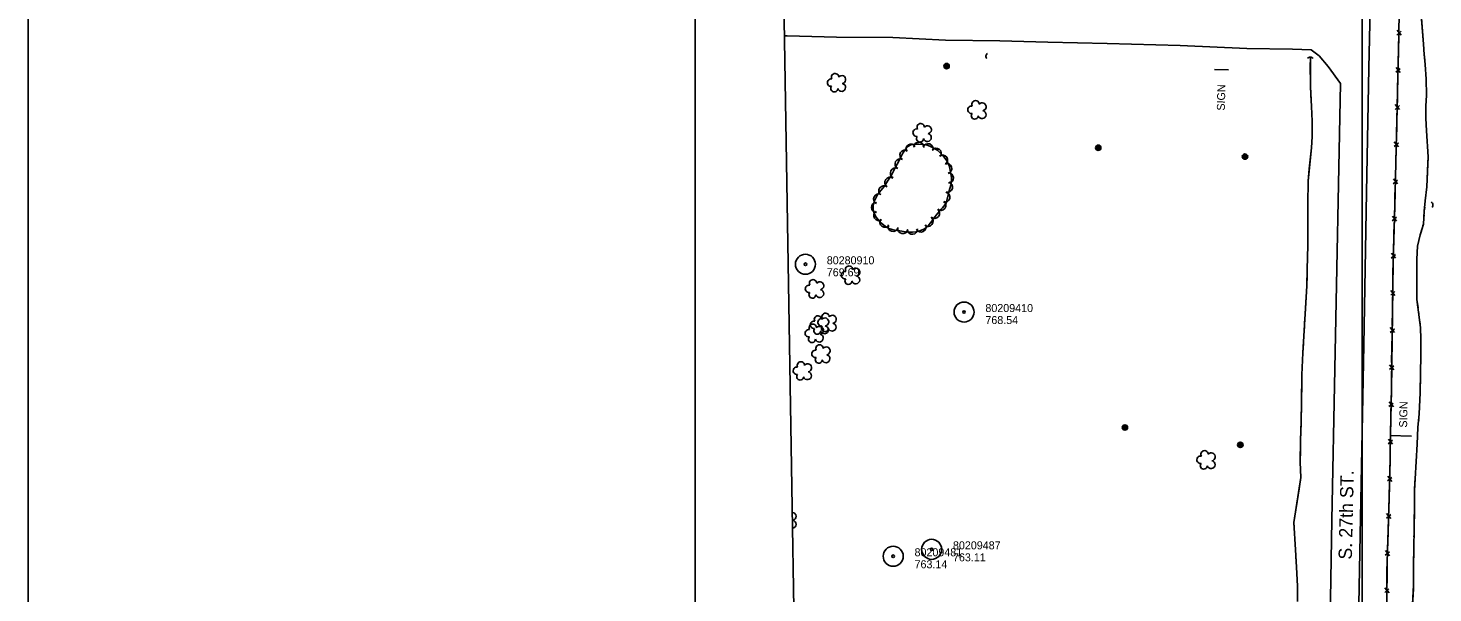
# Model space of a CAD drawing. Extents: x 591954 to 597000, y 198576 to 213500.
# Drawn here: x 593000 to 594053, y 208052 to 208476 of the extents above; entities that cross this region are included whole.
import ezdxf

# ---------------------------------------------------------------- set-up
doc = ezdxf.new("R2010")
doc.units = 0
for name, color, linetype in [('1', 7, 'Continuous'), ('Level 10', 7, 'Continuous'), ('Level 11', 7, 'Continuous'), ('Level 14', 7, 'Continuous'), ('Level 15', 7, 'Continuous'), ('Level 18', 7, 'Continuous'), ('Level 19', 7, 'Continuous'), ('Level 4', 7, 'Continuous'), ('Level 6', 7, 'Continuous')]:
    doc.layers.add(name, color=color, linetype=linetype)

msp = doc.modelspace()

# ---------------------------------------------------------------- linework, layer by layer
at = {"layer": 'Level 10'}
for p, q in [((593000, 207500), (593000, 209000)), ((593500, 207500), (593500, 209000)), ((594000, 207500), (594000, 209000))]:
    msp.add_line(p, q, dxfattribs=at)
at = {"layer": 'Level 11'}
for points in [[(593991.5, 207734.1), (593993.2, 207838.1), (593996.5, 207991.7), (593997.8, 208056.9), (593999.8, 208160.4), (594001.4, 208238.2), (594003.2, 208352.6), (594005, 208445.7), (594007.6, 208557.1), (594009, 208631.5)], [(593567, 208469.8), (593569, 208469.8), (593605.9, 208469), (593648.1, 208468.6), (593687.8, 208466.6), (593728.3, 208466.2), (593764.3, 208465.2), (593808.8, 208464.2), (593863.7, 208462.6), (593913.7, 208460.5), (593947.9, 208460), (593961.7, 208459.4), (593967.7, 208454.9), (593974.6, 208447), (593983.9, 208434.1)], [(593983.9, 208434.1), (593979.6, 208220.4), (593977.3, 208107), (593975.7, 208018.6)]]:
    msp.add_lwpolyline(points, dxfattribs=at)
at = {"layer": 'Level 14'}
for points in [[(593899.8, 208444.3), (593889.4, 208444.6)], [(594036.9, 208169.9), (594020.8, 208170.4)]]:
    msp.add_lwpolyline(points, dxfattribs=at)
for centre, radius in [((593688.5, 208447.2), 2.02), ((593688.4, 208447.2), 1.52), ((593688.5, 208447.2), 1.01), ((593688.5, 208447.2), 0.502), ((593802.2, 208386), 2.02), ((593802.2, 208386), 1.52), ((593802.3, 208386), 1.01), ((593802.3, 208386), 0.502), ((593912.2, 208379.4), 2.02), ((593912.2, 208379.5), 1.52), ((593912.2, 208379.4), 1.01), ((593912.2, 208379.4), 0.502), ((593822.2, 208176.4), 2.02), ((593822.2, 208176.4), 1.52), ((593822.2, 208176.3), 1.01), ((593822.3, 208176.3), 0.502), ((593908.7, 208163.4), 2.02), ((593908.7, 208163.4), 1.52), ((593908.8, 208163.4), 1.01), ((593908.8, 208163.4), 0.502)]:
    msp.add_circle(centre, radius, dxfattribs=at)
at = {"layer": 'Level 15'}
for p, q in [((594029.3, 208470.3), (594026.2, 208474.1)), ((594026.1, 208470.5), (594029.3, 208473.3)), ((594025.3, 208442.7), (594028.6, 208445.4)), ((594028.5, 208442.4), (594025.4, 208446.2)), ((594028, 208414.6), (594024.8, 208418.4)), ((594024.8, 208414.8), (594028, 208417.6)), ((594024, 208387), (594027.3, 208389.7)), ((594027.3, 208386.7), (594024.1, 208390.5)), ((594023.3, 208359.1), (594026.5, 208361.8)), ((594026.5, 208358.9), (594023.4, 208362.7)), ((594022.6, 208331.3), (594025.8, 208334)), ((594025.8, 208331), (594022.7, 208334.8)), ((594021.8, 208303.4), (594025, 208306.1)), ((594025, 208303.2), (594021.9, 208307)), ((594024.6, 208275.3), (594021.4, 208279.1)), ((594021.4, 208275.5), (594024.6, 208278.3)), ((594024.2, 208247.5), (594021, 208251.2)), ((594021, 208247.7), (594024.2, 208250.4)), ((594023.8, 208219.6), (594020.6, 208223.4)), ((594020.6, 208219.8), (594023.8, 208222.6)), ((594020.1, 208192), (594023.3, 208194.7)), ((594023.4, 208191.8), (594020.2, 208195.5)), ((594019.6, 208164.1), (594022.8, 208166.9)), ((594022.8, 208163.9), (594019.7, 208167.7)), ((594019.1, 208136.3), (594022.3, 208139)), ((594022.3, 208136), (594019.2, 208139.8)), ((594018.2, 208108.4), (594021.5, 208111.1)), ((594021.5, 208108.2), (594018.3, 208112)), ((594020.6, 208080.3), (594017.4, 208084.1)), ((594017.3, 208080.6), (594020.6, 208083.3)), ((594016.9, 208052.7), (594020.1, 208055.5)), ((594020.2, 208052.5), (594017, 208056.3))]:
    msp.add_line(p, q, dxfattribs=at)
for points in [[(594011.5, 207735), (594011.8, 207756), (594013.4, 207819.8), (594013.9, 207853.2), (594015.3, 207915.5), (594016.1, 207947.6), (594016.7, 207978.8), (594018.4, 208043.4), (594018.7, 208075.6), (594019.7, 208108), (594020.7, 208140.2), (594021.3, 208172.7), (594021.9, 208204.2), (594023.2, 208300.2), (594024.4, 208341.9), (594025.2, 208374.6), (594026.1, 208406.9), (594026.7, 208438.1), (594027.6, 208471.4), (594027.9, 208504), (594028.7, 208536.2), (594029.2, 208568.7), (594029.8, 208600.4), (594030.8, 208634)], [(594027.3, 208459.2), (594027.6, 208469.2)], [(594027, 208447.9), (594027.3, 208459.2)], [(594026.6, 208431.4), (594026.7, 208438.1), (594026.8, 208441.3)], [(594026.4, 208420), (594026.6, 208431.4)], [(594026, 208403.5), (594026.1, 208406.9), (594026.2, 208413.5)], [(594025.7, 208392.2), (594026, 208403.5)], [(594025.2, 208375.7), (594025.5, 208385.6)], [(594024.9, 208364.3), (594025.2, 208374.6), (594025.2, 208375.7)], [(594024.2, 208336.5), (594024.4, 208341.9), (594024.5, 208347.8)], [(594024.5, 208347.8), (594024.8, 208357.8)], [(594023.8, 208320), (594024.1, 208329.9)], [(594023.4, 208308.6), (594023.8, 208320)], [(594023.1, 208292.1), (594023.2, 208300.2), (594023.3, 208302.1)], [(594022.9, 208280.8), (594023.1, 208292.1)], [(594022.7, 208264.2), (594022.8, 208274.2)], [(594022.5, 208252.9), (594022.7, 208264.2)], [(594022.3, 208236.4), (594022.4, 208246.3)], [(594022.1, 208225.1), (594022.3, 208236.4)], [(594021.9, 208208.5), (594022.1, 208218.5)], [(594021.7, 208197.2), (594021.9, 208204.2), (594021.9, 208208.5)], [(594021.4, 208180.7), (594021.6, 208190.6)], [(594021.2, 208169.4), (594021.3, 208172.7), (594021.4, 208180.7)], [(594020.9, 208152.8), (594021.1, 208162.8)], [(594020.7, 208141.5), (594020.9, 208152.8)], [(594020.2, 208125), (594020.5, 208134.9)], [(594019.9, 208113.6), (594020.2, 208125)], [(594019.4, 208097.1), (594019.7, 208107.1)], [(594019, 208085.8), (594019.4, 208097.1)], [(594018.6, 208069.3), (594018.7, 208075.6), (594018.8, 208079.2)], [(594018.5, 208058), (594018.6, 208069.3)]]:
    msp.add_lwpolyline(points, dxfattribs=at)
for centre, start, end in [((593720.5, 208454.6), 120.5794, 226.819), ((593961.1, 208451.5), 35.2794, 141.519), ((594050.6, 208343.2), 312.9794, 59.219)]:
    msp.add_arc(centre, 2.5, start, end, dxfattribs=at)
at = {"layer": 'Level 18'}
msp.add_lwpolyline([(593688.1, 208344.6), (593689.9, 208351.7), (593690.9, 208355.4), (593692, 208358.8), (593692.1, 208363.7), (593691.3, 208369.3), (593690.4, 208372.8), (593688.2, 208376.9), (593685.8, 208380.1), (593684.3, 208381.8), (593682, 208383.9), (593679, 208385.8), (593675.9, 208387.2), (593673.3, 208388.1), (593671.2, 208388.4), (593667.7, 208388.8), (593665.1, 208388.7), (593662.2, 208388.4), (593659, 208386.7), (593655.6, 208382), (593654.9, 208380.4), (593653.8, 208378.2), (593652.8, 208376), (593651.4, 208373.6), (593649.9, 208370.9), (593648.5, 208367.9), (593646.9, 208365), (593644.8, 208361.7), (593641.6, 208357), (593639.5, 208354.2), (593637, 208351.3), (593634.2, 208345.7), (593633.5, 208342.4), (593633.4, 208339.4), (593634.4, 208336.3), (593635.7, 208334), (593636.9, 208332.4), (593638.6, 208330.3), (593639.9, 208329.2), (593641.5, 208328.1), (593643.5, 208326.6), (593645.2, 208325.6), (593647.7, 208324.7), (593650, 208324.3), (593652.3, 208324), (593657.7, 208322.9), (593660.8, 208322.7), (593663, 208322.8), (593665.5, 208322.9), (593668.4, 208323.7), (593671.4, 208325), (593673, 208326), (593674.6, 208327.4), (593675.5, 208328.5), (593677.4, 208331.1), (593678.2, 208332.3), (593680, 208334.4), (593680.8, 208335.4), (593682, 208336.9), (593683.6, 208338.9), (593684.5, 208339.9), (593685.4, 208341.1), (593688.1, 208344.6)], dxfattribs=at)
for centre, radius, start, end in [((593601.9, 208434.8), 2.78, 78.0716, 279.0826), ((593604.3, 208430.4), 2.61, 140.7797, 358.7123), ((593604.9, 208438.9), 2.78, 1.3946, 209.1675), ((593609.8, 208431.2), 2.97, 196.0745, 79.0477), ((593609.9, 208437.1), 2.97, 278.4237, 139.6575), ((593710.2, 208418.6), 2.78, 1.3946, 209.1675), ((593707.2, 208414.5), 2.78, 78.0716, 279.0826), ((593709.6, 208410.1), 2.61, 140.7797, 358.7123), ((593715.1, 208410.8), 2.97, 196.0745, 79.0477), ((593715.2, 208416.7), 2.97, 278.4237, 139.6575), ((593666.1, 208397.3), 2.78, 78.0716, 279.0826), ((593669.1, 208401.4), 2.78, 1.3946, 209.1675), ((593674.2, 208399.5), 2.97, 278.4237, 139.6575), ((593667.7, 208386.4), 3.85, 358.0589, 178.0435), ((593668.6, 208392.9), 2.61, 140.7797, 358.7123), ((593674.1, 208393.7), 2.97, 196.0745, 79.0477), ((593657.4, 208380.5), 3.85, 59.8995, 239.8841), ((593661.8, 208385), 3.69, 30.7624, 210.7471), ((593674.6, 208385.2), 3.85, 340.9483, 160.933), ((593680.7, 208381.8), 3.84, 321.3979, 141.3826), ((593685.5, 208376.7), 3.85, 305.1599, 125.1445), ((593650.2, 208367), 3.86, 62.5937, 242.5784), ((593653.7, 208373.8), 3.87, 62.1663, 242.1509), ((593688.6, 208370.5), 3.83, 286.6933, 106.678), ((593646.1, 208360.1), 3.87, 56.256, 236.2406), ((593689.1, 208356.5), 3.86, 255.1567, 75.1413), ((593689.8, 208363.4), 3.85, 273.1607, 93.1454), ((593637.6, 208347.6), 3.85, 63.2595, 243.2441), ((593641.5, 208353.7), 3.87, 51.9266, 231.9113), ((593687.1, 208349), 3.87, 256.0559, 76.0405), ((593636, 208341.3), 3.79, 89.9396, 269.9243), ((593637.8, 208335.3), 3.83, 121.6622, 301.6468), ((593679.4, 208336.9), 3.87, 231.1628, 51.1475), ((593684.2, 208342.9), 3.82, 231.5491, 51.5338), ((593642.4, 208330.2), 3.85, 142.299, 322.2837), ((593648.4, 208327.1), 3.83, 163.837, 343.8217), ((593669.4, 208326.7), 3.83, 205.8734, 25.8581), ((593674.5, 208330.9), 3.86, 231.2992, 51.2838), ((593655.7, 208325.5), 3.86, 170.2855, 350.2702), ((593662.9, 208325), 3.85, 183.3457, 3.3304), ((593615.4, 208294.7), 2.78, 1.3946, 209.1675), ((593620.5, 208292.8), 2.97, 278.4237, 139.6575), ((593588.4, 208284.4), 2.78, 1.3946, 209.1675), ((593593.5, 208282.6), 2.97, 278.4237, 139.6575), ((593612.4, 208290.6), 2.78, 78.0716, 279.0826), ((593614.9, 208286.2), 2.61, 140.7797, 358.7123), ((593620.4, 208287), 2.97, 196.0745, 79.0477), ((593585.4, 208280.3), 2.78, 78.0716, 279.0826), ((593587.9, 208275.9), 2.61, 140.7797, 358.7123), ((593593.4, 208276.7), 2.97, 196.0745, 79.0477), ((593588.2, 208251.1), 2.78, 1.3946, 209.1675), ((593589.1, 208253.3), 2.78, 78.0716, 279.0826), ((593592.1, 208257.3), 2.78, 1.3946, 209.1675), ((593594.8, 208255.2), 2.78, 78.0716, 279.0826), ((593597, 208249.6), 2.97, 196.0745, 79.0477), ((593597.2, 208255.5), 2.97, 278.4237, 139.6575), ((593597.8, 208259.3), 2.78, 1.3946, 209.1675), ((593602.7, 208251.6), 2.97, 196.0745, 79.0477), ((593602.9, 208257.5), 2.97, 278.4237, 139.6575), ((593585.2, 208247), 2.78, 78.0716, 279.0826), ((593587.6, 208242.6), 2.61, 140.7797, 358.7123), ((593591.6, 208248.9), 2.61, 140.7797, 358.7123), ((593593.1, 208243.4), 2.97, 196.0745, 79.0477), ((593593.2, 208249.2), 2.97, 278.4237, 139.6575), ((593597.3, 208250.8), 2.61, 140.7797, 358.7123), ((593590.2, 208231.6), 2.78, 78.0716, 279.0826), ((593593.2, 208235.6), 2.78, 1.3946, 209.1675), ((593598.2, 208233.8), 2.97, 278.4237, 139.6575), ((593576.3, 208218.9), 2.78, 78.0716, 279.0826), ((593579.3, 208222.9), 2.78, 1.3946, 209.1675), ((593584.4, 208221.1), 2.97, 278.4237, 139.6575), ((593592.7, 208227.2), 2.61, 140.7797, 358.7123), ((593598.1, 208227.9), 2.97, 196.0745, 79.0477), ((593578.8, 208214.5), 2.61, 140.7797, 358.7123), ((593584.2, 208215.2), 2.97, 196.0745, 79.0477), ((593881.9, 208156.3), 2.78, 1.3946, 209.1675), ((593878.9, 208152.2), 2.78, 78.0716, 279.0826), ((593881.3, 208147.8), 2.61, 140.7797, 358.7123), ((593886.8, 208148.6), 2.97, 196.0745, 79.0477), ((593886.9, 208154.4), 2.97, 278.4237, 139.6575), ((593572.8, 208109.7), 2.97, 278.4237, 88.4284), ((593572.7, 208103.9), 2.97, 277.4855, 79.0477)]:
    msp.add_arc(centre, radius, start, end, dxfattribs=at)
at = {"layer": 'Level 19'}
for points in [[(594037.1, 208029.8), (594038.5, 208058.3), (594038.6, 208072.7), (594038.7, 208087.1), (594038.9, 208099.3), (594039.2, 208116.1), (594039.3, 208129.3), (594039.7, 208137.8), (594041.3, 208163.9), (594041.8, 208176.3), (594042.7, 208186.6), (594043.6, 208202.3), (594043.7, 208217.8), (594043.9, 208229.6), (594044, 208242.7), (594043.7, 208251.4), (594041.1, 208272.4), (594041, 208287.2), (594041.1, 208302.5), (594041.5, 208312.2), (594043.5, 208320.7), (594045.9, 208328.7), (594046.6, 208338.5), (594047.3, 208346.2), (594048.4, 208356.8), (594049.4, 208379.2), (594048.2, 208398.8), (594047.7, 208408.3), (594047.7, 208417.2), (594048.3, 208425.4), (594048, 208437.3), (594047.3, 208448.3), (594046.6, 208455.9), (594046, 208463.6), (594043.9, 208488.5)], [(594046.8, 208454.2), (594046.6, 208455.9), (594046, 208463.6), (594044.4, 208483.1)], [(593961.2, 208453.9), (593961.2, 208431.7), (593961.8, 208421)], [(594048.3, 208425.3), (594048.3, 208425.4), (594048, 208437.3), (594047.3, 208448.3), (594046.8, 208454.2)], [(593961, 208450), (593961.2, 208431.7), (593962, 208417), (593962.5, 208405.9), (593962.6, 208394.4), (593962.1, 208386), (593959.5, 208361.2), (593959.3, 208343.7), (593959.2, 208330.2), (593959.2, 208312.9), (593958.8, 208294.8), (593958.6, 208282.6), (593955.6, 208232.4), (593954.7, 208215.8), (593954.6, 208195), (593954.2, 208179.9), (593953.9, 208166.6), (593953.5, 208150.3), (593954.1, 208139), (593948.8, 208105.3), (593950.1, 208084.6), (593950.7, 208071.7), (593951.5, 208057.6), (593951.5, 208045.9)], [(594047.9, 208419.3), (594048, 208421.3)], [(593962, 208417), (593962, 208417), (593962.1, 208415)], [(593962.3, 208411.1), (593962.4, 208409.1)], [(594047.7, 208413.3), (594047.7, 208415.3)], [(593962.5, 208405.1), (593962.5, 208403.1)], [(594047.8, 208407.3), (594047.7, 208408.3), (594047.7, 208409.3)], [(594049.2, 208374.4), (594049.4, 208379.2), (594048.2, 208398.8), (594048, 208403.3)], [(593962.6, 208399.1), (593962.6, 208394.4), (593962.1, 208386), (593960.4, 208370.2)], [(593960.4, 208370.2), (593959.5, 208361.2), (593959.3, 208343.7), (593959.3, 208341.2)], [(594047.2, 208345.4), (594047.3, 208346.2), (594048.4, 208356.8), (594049.2, 208374.4)], [(593959.3, 208337.2), (593959.2, 208335.2)], [(594046.7, 208339.5), (594046.9, 208341.5)], [(593959.2, 208331.2), (593959.2, 208330.2), (593959.2, 208329.2)], [(594045.6, 208327.5), (594045.9, 208328.7), (594046, 208329.5)], [(594046.2, 208333.5), (594046.4, 208335.5)], [(593959.2, 208319.2), (593959.2, 208312.9), (593958.8, 208294.8), (593958.7, 208290.2)], [(593959.2, 208325.2), (593959.2, 208323.2)], [(594041.1, 208295.1), (594041.1, 208302.5), (594041.5, 208312.2), (594043.5, 208320.7), (594044.4, 208323.7)], [(594041.9, 208266.1), (594041.1, 208272.4), (594041, 208287.2), (594041.1, 208295.1)], [(593958.7, 208290.2), (593958.6, 208282.6), (593957.3, 208261.3)], [(593957.1, 208257.3), (593956.9, 208255.3)], [(594042.6, 208260.2), (594042.4, 208262.2)], [(594043.4, 208254.2), (594043.1, 208256.2)], [(593956.3, 208245.3), (593956.2, 208243.3)], [(593956.7, 208251.3), (593956.6, 208249.3)], [(594043.7, 208215.3), (594043.7, 208217.8), (594043.9, 208229.6), (594044, 208242.7), (594044, 208244.3)], [(594043.8, 208248.2), (594043.8, 208250.2)], [(593956, 208239.3), (593955.6, 208232.4), (593954.7, 208215.8), (593954.7, 208210.3)], [(594042.7, 208186.3), (594042.7, 208186.6), (594043.6, 208202.3), (594043.7, 208215.3)], [(593954.7, 208210.3), (593954.6, 208195), (593954.2, 208181.3)], [(594042.2, 208180.3), (594042.4, 208182.3)], [(593954, 208171.3), (593953.9, 208169.3)], [(593954.1, 208177.3), (593954.1, 208175.3)], [(594041.5, 208168.3), (594041.6, 208170.3)], [(594041.7, 208174.3), (594041.8, 208176.3), (594041.8, 208176.3)], [(593953.7, 208159.3), (593953.5, 208150.3), (593954.1, 208139), (593952.7, 208130.5)], [(593953.9, 208165.3), (593953.8, 208163.3)], [(594039.6, 208135.4), (594039.7, 208137.8), (594041.3, 208163.9), (594041.3, 208164.3)], [(593952.7, 208130.5), (593948.8, 208105.3), (593949, 208101.8)], [(594039, 208106.4), (594039.2, 208116.1), (594039.3, 208129.3), (594039.6, 208135.4)], [(593949.2, 208097.8), (593949.4, 208095.8)], [(594038.8, 208094.4), (594038.9, 208096.4)], [(594038.9, 208100.4), (594039, 208102.4)], [(593949.6, 208091.8), (593949.8, 208089.8)], [(593950, 208085.8), (593950.1, 208084.6), (593950.1, 208083.8)], [(594038.4, 208055.4), (594038.5, 208058.3), (594038.6, 208072.7), (594038.7, 208084.4)], [(594038.7, 208088.4), (594038.8, 208090.4)], [(593950.3, 208079.8), (593950.7, 208071.7), (593951.5, 208057.6), (593951.5, 208050.9)], [(594037, 208026.4), (594037.1, 208029.8), (594038.4, 208055.4)]]:
    msp.add_lwpolyline(points, dxfattribs=at)
at = {"layer": 'Level 4'}
msp.add_lwpolyline([(593564.2, 208601.2), (593566.8, 208481.6), (593580.1, 207675.9)], dxfattribs=at)
at = {"layer": 'Level 6'}
for centre, radius in [((593582.7, 208298.7), 7.5), ((593582.7, 208298.7), 0.96), ((593701.6, 208262.9), 7.5), ((593701.6, 208262.9), 0.96), ((593648.5, 208079.9), 7.5), ((593677.3, 208085.1), 7.5), ((593677.3, 208085.1), 0.96), ((593648.5, 208079.9), 0.96)]:
    msp.add_circle(centre, radius, dxfattribs=at)

# ---------------------------------------------------------------- texts
at = {"layer": '1'}
msp.add_text('S. 27th ST.', height=10, rotation=88.7128, dxfattribs=at).set_placement((593992.3, 208077.3))
at = {"layer": 'Level 14'}
for p in [(593897.1, 208413.8), (594033.7, 208176.3)]:
    msp.add_text('SIGN', height=6, rotation=88.8567, dxfattribs=at).set_placement(p)
at = {"layer": 'Level 6'}
for s, p in [('80280910', (593598.7, 208298.7)), ('769.69', (593598.7, 208289.7)), ('80209410', (593717.6, 208262.9)), ('768.54', (593717.6, 208253.9)), ('80209481', (593664.5, 208079.9)), ('80209487', (593693.3, 208085.1)), ('763.14', (593664.5, 208070.9)), ('763.11', (593693.3, 208076.1))]:
    msp.add_text(s, height=6, dxfattribs=at).set_placement(p)

doc.saveas('drawing.dxf')
